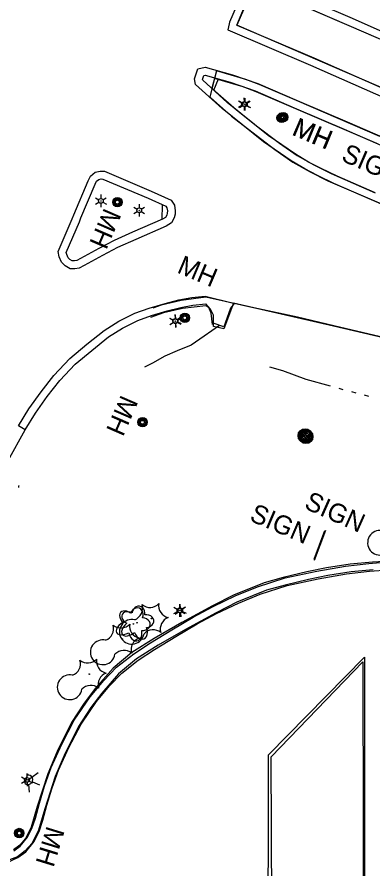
# Model space of a CAD drawing. Extents: x 588843 to 2552415, y 180129 to 269402.
# Drawn here: x 593378.3 to 593491.7, y 185491.8 to 185762.9 of the extents above; entities that cross this region are included whole.
import ezdxf

# ---------------------------------------------------------------- set-up
doc = ezdxf.new("R2010")
doc.units = 0
for name, color, linetype in [('Default', 7, 'Continuous'), ('E_BLD', 7, 'Continuous'), ('E_BLD_HvyDash', 7, 'Continuous'), ('E_DRN', 7, 'Continuous'), ('E_DWY', 7, 'Continuous'), ('E_LAND_Vegetation', 7, 'Continuous'), ('E_LTG', 7, 'Continuous'), ('E_MISCPROP', 7, 'Continuous'), ('E_PATH_Sidewalk', 7, 'Continuous'), ('E_RDWY', 7, 'Continuous'), ('E_RDWY_C_and_G', 7, 'Continuous'), ('E_RDWY_Gravel', 7, 'Continuous'), ('E_SGN', 7, 'Continuous'), ('E_SGN_Text', 7, 'Continuous'), ('E_UTL_MH', 7, 'Continuous'), ('E_UTL_MH_Text', 7, 'Continuous'), ('E_WTR_P', 7, 'Continuous')]:
    doc.layers.add(name, color=color, linetype=linetype)

# ---------------------------------------------------------------- blocks, each defined once
blk = doc.blocks.new('LPOL')
at = {"layer": 'Default'}
for p, q in [((-4, 0), (-1.5, 0)), ((-0.75, 1.3), (-2, 3.46)), ((0.75, 1.3), (2, 3.46)), ((1.5, 0), (4, 0)), ((-2, -3.46), (-0.75, -1.3)), ((2, -3.46), (0.75, -1.3))]:
    blk.add_line(p, q, dxfattribs=at)
for radius in [1.5, 1.5, 1.5, 0.125]:
    blk.add_circle((0, 0), radius, dxfattribs=at)
blk = doc.blocks.new('POLE')
at = {"layer": 'Default'}
for radius in [4.46, 3.35, 2.23, 1.12]:
    blk.add_circle((0, 0), radius, dxfattribs=at)
blk = doc.blocks.new('SIGN')
at = {"layer": 'Default'}
blk.add_text('SIGN', height=12, dxfattribs=at).set_placement((-18.55, -6))
blk = doc.blocks.new('MHO')
at = {"layer": 'Default'}
for centre, radius in [((0.08, -0.12), 3), ((0.08, -0.12), 2.43), ((0.07, -0.15), 1.94), ((0.02, -0.16), 1.21)]:
    blk.add_circle(centre, radius, dxfattribs=at)
blk = doc.blocks.new('MHT')
at = {"layer": 'E_UTL_MH_Text'}
blk.add_text('MH', height=12, dxfattribs=at).set_placement((-9.81, -6))
blk = doc.blocks.new('CULV2')
at = {"layer": 'E_DRN'}
blk.add_arc((20, 15), 24.6, 216.8699, 323.1301, dxfattribs=at)
blk = doc.blocks.new('CTRE')
at = {"layer": 'Default'}
blk.add_circle((0, 0), 0.223, dxfattribs=at)
for centre, start, end in [((-11.97, 8.96), 280.2067, 5.9716), ((1.81, 14.92), 220.2113, 305.9762), ((13.83, 5.89), 160.2113, 245.9762), ((-13.83, -5.9), 340.2113, 65.9762), ((12.03, -9.04), 185.9272, 100.2511), ((-1.81, -14.93), 40.2113, 125.9762)]:
    blk.add_arc(centre, 7.87, start, end, dxfattribs=at)
blk = doc.blocks.new('DTRE')
at = {"layer": 'Default'}
blk.add_circle((-0.18, 0), 0.183, dxfattribs=at)
for centre, major_axis, ratio in [((-1.87, 5.32), (1.36, -4.98), 0.782863), ((4.06, 2.74), (-5.27, -2.93), 0.691916), ((-5.87, 0.15), (4.93, -0.12), 0.832022), ((-2.49, -5.24), (1.8, 4.86), 0.716896), ((3.54, -3.71), (-5.01, 4.58), 0.560249)]:
    blk.add_ellipse(centre, major_axis=major_axis, ratio=ratio, start_param=1.570796, end_param=4.712389, dxfattribs=at)
blk = doc.blocks.new('MHO_3')
at = {"layer": 'E_UTL_MH'}
for centre, radius in [((0.3, -0.4), 9.84), ((0.3, -0.4), 7.98), ((0.2, -0.5), 6.35), ((0.1, -0.5), 3.97)]:
    blk.add_circle(centre, radius, dxfattribs=at)
blk = doc.blocks.new('MHT_3')
at = {"layer": 'E_UTL_MH_Text'}
blk.add_text('MH', height=39.37, dxfattribs=at).set_placement((-32.2, -19.7))
blk = doc.blocks.new('LPOL_4')
at = {"layer": 'E_LTG'}
for p, q in [((-13.1, 0), (-4.9, 0)), ((-2.5, 4.3), (-6.6, 11.4)), ((2.5, 4.3), (6.6, 11.4)), ((4.9, 0), (13.1, 0)), ((-6.6, -11.4), (-2.5, -4.3)), ((6.6, -11.4), (2.5, -4.3))]:
    blk.add_line(p, q, dxfattribs=at)
for radius in [4.92, 4.92, 4.92, 0.41]:
    blk.add_circle((0, 0), radius, dxfattribs=at)
blk = doc.blocks.new('POLE_3')
at = {"layer": 'E_MISCPROP'}
for radius in [14.6, 11, 7.32, 3.66]:
    blk.add_circle((0, 0), radius, dxfattribs=at)
blk = doc.blocks.new('SIGN_3')
at = {"layer": 'E_SGN'}
blk.add_text('SIGN', height=39.37, dxfattribs=at).set_placement((-56.1, -19.7))
blk = doc.blocks.new('DTRE_4')
at = {"layer": 'E_LAND_Vegetation'}
blk.add_circle((-0.6, 0), 0.601, dxfattribs=at)
for centre, major_axis, ratio in [((-6.1, 17.5), (4.5, -16.3), 0.782863), ((13.3, 9), (-17.3, -9.6), 0.691916), ((-19.3, 0.5), (16.2, -0.4), 0.832022), ((-8.2, -17.2), (5.9, 15.9), 0.716896), ((11.6, -12.2), (-16.4, 15), 0.560249)]:
    blk.add_ellipse(centre, major_axis=major_axis, ratio=ratio, start_param=1.570796, end_param=4.712389, dxfattribs=at)

msp = doc.modelspace()

# ---------------------------------------------------------------- linework, layer by layer
at = {"layer": 'E_BLD'}
msp.add_lwpolyline([(593458.13, 185312.89), (593458.4, 185528.09), (593488.96, 185559.22), (593489.06, 185344.31), (593528.46, 185383.26), (593528.33, 185390.83), (593522.65, 185390.76), (593522.55, 185401.38), (593528.2, 185401.37), (593528.15, 185411.36), (593581.17, 185464.3), (593649.13, 185395.93), (593595.41, 185342.82)], dxfattribs=at)
at = {"layer": 'E_BLD_HvyDash'}
msp.add_lwpolyline([(593460.24, 185314.65), (593459.25, 185527.52), (593488.47, 185557.73), (593488.88, 185343.2)], dxfattribs=at)
at = {"layer": 'E_DWY'}
for points in [[(593499.1, 185589.89), (593491.54, 185589.46), (593484.44, 185588.82), (593476.88, 185587.6), (593470.61, 185586.35), (593463.06, 185584.57), (593457, 185582.85), (593447.28, 185578.93), (593440.56, 185575.49), (593430.77, 185570.2), (593421.94, 185565.18), (593414.88, 185560.66), (593408.89, 185555.68), (593403.34, 185549.35), (593399.72, 185544.59), (593395.67, 185538.39), (593391.32, 185529.73), (593388.12, 185522.04), (593384.72, 185511.62), (593382.85, 185505.08), (593381.01, 185501.44), (593379.15, 185499.34), (593377.21, 185497.84)], [(593377.28, 185497.59), (593379.34, 185499.04), (593381.64, 185501.85), (593383.04, 185504.62), (593384.16, 185507.99), (593385.43, 185512.73), (593387.05, 185518.09), (593389.21, 185524.12), (593392.53, 185531.54), (593396.54, 185539.17), (593401.58, 185546.58), (593405.92, 185551.77), (593409.98, 185555.99), (593415.47, 185560.24), (593420.78, 185563.71), (593427.59, 185567.88), (593434.41, 185571.95), (593440.74, 185575.33), (593447.82, 185578.7), (593454.85, 185581.62), (593463.68, 185584.39), (593473.77, 185586.58), (593482.92, 185588.16), (593490.32, 185589.04), (593496.45, 185589.5)], [(593491.72, 185586.97), (593484.75, 185586.34), (593477.33, 185585.14), (593471.14, 185583.91), (593463.69, 185582.15), (593457.81, 185580.49), (593448.32, 185576.66), (593441.73, 185573.28), (593431.98, 185568.01), (593423.23, 185563.04), (593416.36, 185558.64), (593410.64, 185553.89), (593405.28, 185547.76), (593401.76, 185543.14), (593397.84, 185537.14), (593393.6, 185528.68), (593390.47, 185521.17), (593387.11, 185510.88), (593385.19, 185504.16), (593383.09, 185500.02), (593380.87, 185497.51), (593378.43, 185495.62), (593375.01, 185494.39)], [(593375.16, 185493.89), (593378.52, 185495.41), (593381.06, 185497.19), (593383.74, 185500.47), (593385.36, 185503.66), (593386.56, 185507.27), (593387.84, 185512.04), (593389.43, 185517.3), (593391.53, 185523.19), (593394.78, 185530.45), (593398.69, 185537.88), (593403.58, 185545.07), (593407.79, 185550.1), (593411.65, 185554.12), (593416.92, 185558.2), (593422.11, 185561.6), (593428.88, 185565.74), (593435.64, 185569.77), (593441.86, 185573.1), (593448.83, 185576.41), (593455.7, 185579.27), (593464.32, 185581.97), (593474.24, 185584.12), (593483.28, 185585.68), (593490.56, 185586.55), (593496.58, 185587)]]:
    msp.add_lwpolyline(points, dxfattribs=at)
at = {"layer": 'E_LTG'}
for p, q in [((593381.64, 185522.08), (593381.68, 185521.65)), ((593383.05, 185521.03), (593385.08, 185522.49)), ((593383.2, 185519.54), (593385.47, 185518.51)), ((593381.98, 185518.66), (593382.22, 185516.17))]:
    msp.add_line(p, q, dxfattribs=at)
msp.add_lwpolyline([(593381.51, 185521.62), (593380.81, 185519.05)], dxfattribs=at)
msp.add_circle((593381.83, 185520.16), 0.125, dxfattribs=at)
msp.add_arc((593381.83, 185520.16), 1.5, 227.3906, 102.161, dxfattribs=at)
at = {"layer": 'E_PATH_Sidewalk'}
for points in [[(593440.96, 185739.62), (593442.48, 185743.2)], [(593424.55, 185698.53), (593424.66, 185703.17)]]:
    msp.add_lwpolyline(points, dxfattribs=at)
at = {"layer": 'E_RDWY'}
msp.add_lwpolyline([(593453.69, 185773.4), (593523.56, 185743.19), (593588.11, 185715.4), (593631.1, 185696.92), (593667.51, 185681.1), (593666.73, 185678.74), (593618.51, 185694.03), (593571.62, 185708.83), (593555.14, 185714.19), (593536.4, 185722.25), (593496.73, 185739.41), (593448.26, 185760.34), (593453.69, 185773.4)], close=True, dxfattribs=at)
for points in [[(593438.25, 185674.1), (593447.3, 185671.82), (593444.14, 185663.69), (593440.84, 185664.39), (593440.84, 185668.04), (593439.96, 185669.96), (593438.47, 185671.6)], [(593805.06, 185499.36), (593796.08, 185505.71), (593778.99, 185517.59), (593765.58, 185526.62), (593750.52, 185536.77), (593736.83, 185546.06), (593725.23, 185553.81), (593714.32, 185561.29), (593702.05, 185569.53), (593690.43, 185577.12), (593681.49, 185583.28), (593656.92, 185594.04), (593626.9, 185606.88), (593604.28, 185616.72), (593578.06, 185627.87), (593554.17, 185638.2), (593528.97, 185649.12), (593509.99, 185657.21), (593506.4, 185658.17), (593479.1, 185664.49), (593455.91, 185669.88), (593438.41, 185673.77)], [(593698.01, 185571.94), (593688.62, 185578.29), (593681.05, 185583.59), (593675.17, 185586.22), (593662.43, 185591.77), (593651.91, 185596.35), (593640.5, 185601.19), (593625.4, 185607.53), (593613.63, 185612.79), (593601.92, 185617.92), (593588.88, 185623.58), (593576.37, 185628.83), (593565.9, 185633.32), (593550.87, 185639.79), (593539.52, 185644.78), (593529.63, 185649.16), (593515.76, 185655.12), (593508.93, 185658), (593506.71, 185658.75), (593494.07, 185661.19), (593479.18, 185664.59), (593467.68, 185667.38), (593453.78, 185670.37), (593447.3, 185671.82)], [(593282.48, 185343.12), (593285.41, 185356.31), (593288.47, 185369.55), (593291.42, 185382.49), (593295.56, 185397.86), (593299.32, 185413.37), (593304.07, 185430.15), (593305.83, 185435.64), (593311.64, 185457.14), (593316.6, 185472.82), (593321.43, 185487.25), (593327.9, 185506.35), (593333.84, 185524.27), (593339.47, 185539.74), (593344.26, 185551.86), (593348.77, 185563.29), (593354.98, 185579.26), (593359.35, 185589.84), (593364.2, 185600.61), (593369.48, 185612.01), (593375.46, 185621.77), (593380.94, 185631.55)]]:
    msp.add_lwpolyline(points, dxfattribs=at)
at = {"layer": 'E_RDWY_C_and_G'}
msp.add_line((593380.94, 185631.55), (593378.81, 185632.85), dxfattribs=at)
for points in [[(593448.13, 185766.21), (593446.03, 185761.25), (593445.89, 185760.73), (593445.4, 185758.88), (593471.82, 185747.59), (593502.39, 185734.18), (593537.96, 185718.62), (593551.21, 185713.11), (593555.3, 185711.56), (593576.13, 185704.66), (593609.59, 185694.25), (593642.06, 185683.63), (593668.03, 185675.84), (593670.7, 185682.2), (593650.33, 185690.99), (593611.9, 185707.52), (593580.22, 185721.35), (593554.46, 185732.38), (593530.38, 185742.76), (593496.85, 185757.3), (593485.12, 185762.4), (593452.33, 185776.58)], [(593484.13, 185760.1), (593453.68, 185773.27), (593450.44, 185765.26), (593448.36, 185760.33), (593472.81, 185749.89), (593503.4, 185736.47), (593538.94, 185720.91), (593552.13, 185715.43), (593556.13, 185713.91), (593576.9, 185707.03), (593610.35, 185696.63), (593642.8, 185686.01), (593666.59, 185678.87), (593667.44, 185680.89), (593649.35, 185688.7), (593610.91, 185705.23), (593579.23, 185719.06), (593553.48, 185730.09), (593529.39, 185740.47), (593495.86, 185755.01)], [(593396.36, 185699.94), (593400.91, 185710.76), (593401.66, 185712.3), (593403.2, 185713.54), (593404.8, 185713.89), (593406.19, 185713.86), (593421.03, 185707.54), (593427.44, 185704.66), (593428.49, 185703.06), (593428.68, 185701.26), (593428.62, 185700.21), (593428.37, 185699.04), (593427.53, 185697.39), (593425.8, 185696.34), (593416.1, 185692.14), (593410.35, 185689.56), (593405.49, 185687.05), (593399.7, 185683.88), (593398.11, 185683.02), (593396.75, 185682.8), (593395.24, 185682.83), (593393.64, 185683.7), (593392.51, 185684.88), (593391.71, 185686.61), (593391.42, 185688.32), (593395.86, 185698.72), (593396.36, 185699.94)], [(593398.66, 185698.97), (593403.19, 185709.73), (593403.66, 185710.71), (593404.31, 185711.22), (593405.05, 185711.39), (593405.65, 185711.37), (593420.02, 185705.25), (593425.75, 185702.68), (593426.07, 185702.19), (593426.18, 185701.2), (593426.14, 185700.54), (593426, 185699.89), (593425.63, 185699.16), (593424.65, 185698.57), (593415.09, 185694.43), (593409.26, 185691.81), (593404.32, 185689.25), (593398.5, 185686.08), (593397.3, 185685.42), (593396.58, 185685.31), (593395.9, 185685.32), (593395.17, 185685.71), (593394.6, 185686.31), (593394.12, 185687.36), (593394, 185688.02), (593398.15, 185697.74), (593398.66, 185698.97)]]:
    msp.add_lwpolyline(points, close=True, dxfattribs=at)
for points in [[(593504.48, 185699.01), (593491.16, 185704.76), (593479.18, 185709.97), (593474.04, 185712.49), (593469.96, 185714.56), (593465.61, 185717.14), (593456.77, 185723.22), (593443.6, 185733.86), (593435.2, 185741.46), (593434.79, 185743.24), (593435.92, 185746.4), (593438.25, 185746.97), (593446.89, 185744.56), (593455.05, 185741.76), (593467.57, 185736.35), (593483.44, 185729.54), (593501.05, 185721.93)], [(593492.16, 185707.05), (593480.22, 185712.24), (593475.16, 185714.72), (593471.17, 185716.76), (593466.96, 185719.25), (593458.27, 185725.23), (593445.23, 185735.76), (593437.46, 185742.78), (593437.39, 185743.09), (593437.82, 185744.3), (593438.21, 185744.39), (593446.14, 185742.17), (593454.14, 185739.43), (593466.58, 185734.05), (593482.46, 185727.24), (593500.06, 185719.64)], [(593493.87, 185724.91), (593467.31, 185736.33), (593455.43, 185741.46), (593451.14, 185743.04), (593441.87, 185745.75), (593441.33, 185743.74), (593439.66, 185737.51), (593439.88, 185737.31), (593446.64, 185731.41), (593453.07, 185726.35), (593460.38, 185720.77), (593466.16, 185716.77), (593471.67, 185713.63), (593477.35, 185710.81), (593491.41, 185704.69), (593531.85, 185687.32)], [(593492.88, 185722.62), (593466.32, 185734.03), (593454.5, 185739.14), (593450.36, 185740.67), (593441.22, 185743.33), (593440.39, 185740.23), (593441.54, 185739.17), (593448.24, 185733.34), (593454.6, 185728.33), (593461.85, 185722.79), (593467.49, 185718.89), (593472.85, 185715.84), (593478.4, 185713.08), (593492.4, 185706.98)], [(593378.81, 185632.85), (593382.08, 185638.2), (593385.95, 185643.68), (593390.06, 185648.82), (593395.1, 185654.22), (593400.5, 185658.77), (593406.02, 185663.18), (593410.69, 185666.1), (593415.81, 185668.62), (593420.36, 185670.3), (593425.46, 185671.79), (593429.89, 185672.89), (593433.95, 185673.71), (593438.25, 185674.1)], [(593380.94, 185631.55), (593384.17, 185636.83), (593387.95, 185642.17), (593391.96, 185647.19), (593396.83, 185652.41), (593402.09, 185656.84), (593407.47, 185661.14), (593411.91, 185663.91), (593416.8, 185666.32), (593421.14, 185667.93), (593426.11, 185669.37), (593430.44, 185670.45), (593434.31, 185671.23), (593438.47, 185671.6)], [(593438.41, 185673.77), (593430.58, 185672.67), (593424.24, 185671.19), (593421.54, 185670.22)], [(593438.48, 185670.97), (593430.99, 185670.2), (593424.95, 185668.79), (593420.85, 185667.32)]]:
    msp.add_lwpolyline(points, dxfattribs=at)
at = {"layer": 'E_RDWY_Gravel'}
msp.add_lwpolyline([(593447.48, 185671.75), (593446.27, 185670.21), (593444.16, 185664.32), (593441.13, 185665.43), (593440.59, 185665.04), (593440.11, 185668.67), (593439.42, 185670.46), (593438.48, 185670.97)], dxfattribs=at)
at = {"layer": 'E_SGN'}
msp.add_line((593476.53, 185599.48), (593472.9, 185589.91), dxfattribs=at)
msp.add_lwpolyline([(593472.96, 185590.33), (593476.39, 185599.52)], dxfattribs=at)
at = {"layer": 'E_WTR_P'}
for points in [[(593442.75, 185664.71), (593437.88, 185661.38), (593433.75, 185658.46), (593429.27, 185656.65), (593425.34, 185654.95), (593421.47, 185652.76), (593418.87, 185651.47)], [(593478.18, 185645.44), (593470.37, 185647.61), (593462.93, 185650.31), (593458.83, 185651.52)], [(593482.23, 185644.31), (593480.88, 185644.69)], [(593486.29, 185643.24), (593484.93, 185643.6)], [(593490.35, 185642.17), (593489, 185642.53)]]:
    msp.add_lwpolyline(points, dxfattribs=at)

# ---------------------------------------------------------------- block references
at = {"layer": 'E_DRN', "xscale": 0.015151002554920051, "yscale": 0.01515100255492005, "rotation": -106.42179015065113}
msp.add_blockref('CULV2', (593378.98, 185613.8), dxfattribs=at)
at = {"layer": 'E_LAND_Vegetation'}
for name, p, xscale, yscale, rotation in [('CTRE', (593500.45, 185599.32), 0.49999999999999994, 0.5, -113.47546916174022), ('CTRE', (593421.12, 185571.45), 0.49999999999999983, 0.4999999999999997, -109.30334864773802), ('DTRE', (593415.35, 185569.69), 0.49999999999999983, 0.4999999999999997, -109.30334864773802), ('DTRE_4', (593416.53, 185570.04), 0.1524003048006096, 0.1524003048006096, -97.36026881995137), ('CTRE', (593411.86, 185564.92), 0.49999999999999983, 0.4999999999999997, -109.30334864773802), ('CTRE', (593401.32, 185553.78), 0.49999999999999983, 0.4999999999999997, -109.30334864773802)]:
    msp.add_blockref(name, p, dxfattribs=dict(at, xscale=xscale, yscale=yscale, rotation=rotation))
at = {"layer": 'E_LTG'}
for name, p, xscale, yscale, rotation in [('LPOL', (593450.6, 185735.22), 0.5000000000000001, 0.5, -89.67337617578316), ('LPOL_4', (593450.87, 185735.13), 0.1524003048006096, 0.1524003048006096, -89.2544447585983), ('LPOL', (593405.02, 185704.4), 0.5000000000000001, 0.5, -89.67337617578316), ('LPOL', (593417.22, 185701.41), 0.5000000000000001, 0.5, -89.67337617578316), ('LPOL_4', (593428.71, 185666.21), 0.1524003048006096, 0.15240030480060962, -84.36014555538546), ('LPOL', (593428.73, 185666.11), 0.5000000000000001, 0.5, -89.67337617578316), ('LPOL', (593430.01, 185574.06), 0.5000000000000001, 0.5, -89.67337617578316), ('LPOL_4', (593430.31, 185574.06), 0.1524003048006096, 0.15240030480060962, -84.36014555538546), ('LPOL', (593381.48, 185520.14), 0.5000000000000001, 0.5, -89.67337617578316)]:
    msp.add_blockref(name, p, dxfattribs=dict(at, xscale=xscale, yscale=yscale, rotation=rotation))
at = {"layer": 'E_MISCPROP'}
for name, p, xscale, yscale, rotation in [('POLE_3', (593470.05, 185629.67), 0.1524003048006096, 0.15240030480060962, -84.36014555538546), ('POLE', (593470.34, 185629.37), 0.5000000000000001, 0.5, -89.67337617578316)]:
    msp.add_blockref(name, p, dxfattribs=dict(at, xscale=xscale, yscale=yscale, rotation=rotation))
at = {"layer": 'E_SGN_Text'}
for name, p, xscale, yscale, rotation in [('SIGN', (593490.97, 185716.37), 0.49999999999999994, 0.5000000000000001, -23.33669759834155), ('SIGN', (593479.15, 185605.64), 0.49999999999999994, 0.5, -23.968730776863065), ('SIGN_3', (593461.07, 185602.15), 0.15240030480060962, 0.1524003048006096, -23.10843445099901)]:
    msp.add_blockref(name, p, dxfattribs=dict(at, xscale=xscale, yscale=yscale, rotation=rotation))
at = {"layer": 'E_UTL_MH'}
for name, p, xscale, yscale, rotation in [('MHO', (593462.58, 185730.96), 0.49999999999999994, 0.5000000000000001, -23.33669759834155), ('MHO_3', (593463.08, 185731.11), 0.1524003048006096, 0.15240030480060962, -22.30595810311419), ('MHO', (593410.27, 185704.09), 0.5000000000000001, 0.4999999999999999, -23.108396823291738), ('MHO_3', (593431.74, 185667.26), 0.1524003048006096, 0.15240030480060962, -23.03770799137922), ('MHO', (593418.26, 185634.03), 0.49999999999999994, 0.5, -23.968730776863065), ('MHO_3', (593378.95, 185503.19), 0.1524003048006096, 0.15240030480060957, 72.95030273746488)]:
    msp.add_blockref(name, p, dxfattribs=dict(at, xscale=xscale, yscale=yscale, rotation=rotation))
at = {"layer": 'E_UTL_MH_Text'}
for name, p, xscale, yscale, rotation in [('MHT', (593471.2, 185726.39), 0.49999999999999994, 0.5000000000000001, -23.33669759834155), ('MHT_3', (593471.32, 185726.39), 0.1524003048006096, 0.15240030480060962, -22.30595810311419), ('MHT', (593406.96, 185696.75), 0.5, 0.5, -113.30533143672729), ('MHT_3', (593434.64, 185682.54), 0.1524003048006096, 0.15240030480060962, -23.03770799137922), ('MHT', (593412.31, 185637.26), 0.49999999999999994, 0.5, -113.47546916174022), ('MHT_3', (593389.24, 185500.16), 0.1524003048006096, 0.15240030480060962, -107.04969726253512)]:
    msp.add_blockref(name, p, dxfattribs=dict(at, xscale=xscale, yscale=yscale, rotation=rotation))

doc.saveas('drawing.dxf')
